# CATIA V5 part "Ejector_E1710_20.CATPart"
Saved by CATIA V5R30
Part number: Vyhazovac_4x160_7
Nomenclature: E1710/4x160
Description: MEUSBURGER
Property "Material": "1.221"
Publications: "__DrillHole", "Base"
Bounding box of the stored display mesh (mm): x -3.996 to 3.996, y -3.999 to 3.999, z 0 to 152
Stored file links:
  E:\Bakalarka\Model\Forma_v7\Ejector_E1710_20.CATPart
  E:\dev\MoldDesign\intel_a\startup\components\MoldCatalog\Ejector\Meusburger\Ejector_E1710\TableE1710.txt
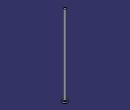
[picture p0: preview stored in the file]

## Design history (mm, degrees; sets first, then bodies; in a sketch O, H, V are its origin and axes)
Parameters
  Ref = "E1710/4x160" {design table}
  D1 = 4 mm {design table}
  D3 = 8 mm {design table}
  L = 160 mm {design table}
  L3 = 3 mm {design table}
  R = 0.3 mm {design table}
  k_d3 = 9 mm {design table}
  k_d1 = 4.2 mm {design table}
  k_F = 0.3 mm {design table}
  kl = 17 mm {design table}
  Mat = "1.221" {design table}
  HeatTreat = "ISO6751" {design table}
  Offset_Parting = 10 mm
  Anti_Rotation = "Normal"
  Anti_Rotation_D = 2.3 mm
  Anti_Rotation_D_Icut = 2.3 mm
  Add_Length_L = 0.8377 mm
  Add_Length_D3 = 0 mm
  SupplierRef = "Meusburger 2017"
  BmpRef = "F_MldEjectorD1"
  DrillHole_Length = 225 mm
  ValidationTest = false
  Anti_Rotation_D_min = 2.3 mm {= OffSet_D1 /2}
  Anti_Rotation_D_max = 3.925 mm {= D3/2-0.075mm}
  Anti_Rotation_D_ref = 2.3 mm {= Anti_Rotation_D}
  Anti_Rotation_D_Icut_ref = 2.3 mm {= Anti_Rotation_D_Icut}
  Anti_Rotation_Ref_Icut = 2.3246 mm
  Offset_L = 20 mm
  D = 4 mm {= D1}
  OffSet_D1 = 4.6 mm {= D1+2*R}
  OffSet_D3 = 9 mm {= D3+1mm}
  XG_Split = 156 mm
  YG_Split = 21.5 mm
  ZG_Split = -198 mm
  DirX_Split = 0 mm
  DirY_Split = 0 mm
  DirZ_Split = 1 mm
Set1 "BaseBody"
  Point1 "Base": (0, 0, 0)
  Plane1: type Offset, RefPlane xy-plane, Offset 225 {= DrillHole_Length}, reversed
  Sketch1 "Sketch.2" on xy-plane, origin (0, 0, 0), H (1, 0, 0), V (0, 1, 0)
    point P1 (-0.46, 1.1623)
    point P2 (0.46, 1.1623)
    construction line L1 (-0.46, 1.1623) -> (0.46, 1.1623)
    point P3 (0.46, -1.1623)
    line L2 (0.46, -1.1623) -> (0.46, 1.1623)
    point P4 (-0.46, -1.1623)
    construction line L3 (0.46, -1.1623) -> (-0.46, -1.1623)
    line L4 (-0.46, 1.1623) -> (-0.46, -1.1623)
    point P5 (-0.21, 1.1623)
    arc A1 centre (-0.21, 1.1623) radius 0.25 from (-0.21, 1.4123) to (-0.46, 1.1623) ccw
    point P7 (0.21, 1.1623)
    point P8 (0.21, 1.4123)
    arc A2 centre (0.21, 1.1623) radius 0.25 from (0.46, 1.1623) to (0.21, 1.4123) ccw
    line L5 (-0.21, 1.4123) -> (0.21, 1.4123)
    point P9 (-0.46, -1.1623)
    arc A3 centre (-0.21, -1.1623) radius 0.25 from (-0.46, -1.1623) to (-0.21, -1.4123) ccw
    point P11 (0.21, -1.4123)
    line L6 (-0.21, -1.4123) -> (0.21, -1.4123)
    point P12 (0.46, -1.1623)
    arc A4 centre (0.21, -1.1623) radius 0.25 from (0.21, -1.4123) to (0.46, -1.1623) ccw
    point P14 (-0.46, 1.1623)
    point P15 (-0.46, -1.1623)
    point P16 (0.46, 1.1623)
    point P17 (0.46, -1.1623)
    reference projected circle E1 centre (0, 0) radius 1.25 from edge [face of Shaft1 from Sketch2.L3 | face of Shaft1 from Sketch2.L4]
    reference projected circle E2 centre (0, 0) radius 1.25 from edge [face of Shaft1 from Sketch2.L3 | face of Shaft1 from Sketch2.L4]
    reference projected circle E3 centre (0, 0) radius 1.25 from edge [face of Shaft1 from Sketch2.L3 | face of Shaft1 from Sketch2.L4]
    reference projected circle E4 centre (0, 0) radius 1.25 from edge [face of Shaft1 from Sketch2.L3 | face of Shaft1 from Sketch2.L4]
    point P18 (-0.46, -1.1623)
    point P19 (-0.21, -1.4123)
    point P20 (0.21, -1.4123)
    point P21 (0.46, -1.1623)
    point P22 (-0.21, -1.4123)
    point P23 (0.21, -1.4123)
    distance P14 P15 = 2.3246 (reference)
    distance P16 P17 = 2.3246 (reference)
    distance L1 P14 = 0 (reference)
    radius A1 = 2
    distance L4 V = 2.31
    distance L2 V = 3.935
    distance L5 L6 = 8
    horizontal: L1 H, L3 H, L5 H
    vertical: L2 V, L4 V
    coincidence: P5 L1, P7 L1, P3 P12, P14 L4, P15 L4, P16 L2, P17 L2, P14 E1, P15 E2, P16 E3, P17 E4, P3 P21, P4 P18, P20 P23, P19 P22
    tangency: A1 L4, A2 L2, A2 L5, A1 L5
    symmetry: P1 P9 H, A1 A3 H, P8 P11 H, L5 L6 H, P2 P12 H, A2 A4 H
  DatumSurface1
  DatumSurface2
Body1 "PartBody" (main body)
  Sketch2 "Sketch.1" on zx-plane, origin (0, 0, 0), H (-1, 0, 0), V (0, 0, 1)
    point P1 (0, 160)
    line L1 (2, 160) -> (0, 160)
    line L2 (2, 3) -> (2, 160)
    line L3 (4, 3) -> (2, 3)
    line L4 (4, 0) -> (4, 3)
    point P5 (0, 0)
    line L5 (0, 0) -> (4, 0)
    point P6 (0, 160)
    axis line L6 (0, 160) -> (0, 0)
    point P7 (0, 0)
    point P8 (2, 3)
    point P9 (2, 3)
    line L7 (0, 160) -> (0, 0)
    distance L5 L3 = 3 {= L3}
    distance L5 L1 = 160 {= L}
    distance L2 L6 = 2 {= D1 /2}
    distance L4 L6 = 4 {= D3 /2}
    coincidence: L6 P5, P1 L6, L5 H, L6 V, P7 O, P6 P1, P8 P9
    vertical: L2 V, L7 V
    horizontal: L1 H
  Shaft1 "Shaft.1": profile Sketch2, axis Sketch2.L6, angle 360
  Pocket1 "Pocket.1": profile Sketch1, direction (0, 0, 1), length 4, outer side, deactivated
  Pocket2 "Pocket.2": profile Sketch1, direction (0, 0, 1), length 4, outer side, deactivated
  Fillet1: radius 0.3 {= R}, on edge [face of Shaft1 from Sketch2.L2 | face of Shaft1 from Sketch2.L3]
  Pocket3: profile face of Shaft1 from Sketch2.L1, direction along face of DatumSurface1, up to face of DatumSurface2
Body2 "__DrillHole"
  Sketch3 "Sketch.3" on face of Shaft1, origin (0, 0, 0), H (1, 0, 0), V (0, -1, 0)
    point P1 (0, 0)
    reference projected point E1 (0, 0) from Point1
    coincidence: E1 P1
  Hole1 "Hole.1": placed by Sketch3, at (0, 0, 0) direction (0, 0, 1), diameter 4.6 {= OffSet_D1}, depth 140 {= L-Offset_L}
  Sketch4 "Sketch.4" on face of Shaft1, origin (0, 0, 0), H (1, 0, 0), V (0, -1, 0)
    point P1 (0, 0)
    reference projected point E1 (0, 0) from Point1
    coincidence: E1 P1
  Hole2 "Hole.2": placed by Sketch4, at (0, 0, 0) direction (0, 0, 1), diameter 4 {= D1}, depth 160 {= L}
  Sketch5 "Sketch.5" on face of Shaft1 from Sketch2.L3, origin (0, 0, 3), H (1, 0, 0), V (0, 1, 0)
    point P1 (0, 0)
    reference projected point E1 (0, 0) from Point1
    coincidence: E1 P1
  Hole3 "Hole.3": placed by Sketch5, at (0, 0, 3) direction (0, 0, -1), diameter 9 {= OffSet_D3}, depth 228 {= L3 +DrillHole_Length}
  Chamfer1: length 0.3 {= k_F}, angle 45, on edge [face of Hole1 | face of Hole3]
  Body3 "__Body.1"
    Pocket4 "Pocket.3": profile Sketch1, direction (0, 0, -1), length 225, opposite side length 3, deactivated
  Assemble1: tool Body3
  Chamfer2: length 0.3 {= k_F}, angle 45, on edge [start face of Pocket4 | face of Hole1], deactivated
  Body4 "__Body.2"
    Pocket5 "Pocket.4": profile Sketch1, direction (0, 0, -1), length 225, opposite side length 3, deactivated
  Assemble2: tool Body4
  Chamfer3: length 0.3 {= k_F}, angle 45, on edge [start face of Pocket5 | face of Hole1], deactivated
Relations
  design table "TableE1710", configuration 187, drives Ref, D1, D3, L, L3, R, k_d3, k_d1, k_F, kl, Mat, HeatTreat
  Offset_L = 20mm (deactivated)
  rule "Cut_Head_rule":
    let sketch_cut (length)
    let PartBody_Pocket_Sketch (Boolean)
    let I_PartBody_Pocket (Boolean)
    let D_PartBody_Pocket (Boolean)
    let N_DrillHole_Hole (Boolean)
    let N_DrillHole_Hole_Sketch (Boolean)
    let I_DrillHole_Pocket (Boolean)
    let D_DrillHole_Pocket (Boolean)
    /* --------------------------------------------------------------------------------------*/
    if Anti_Rotation =="Normal"
    {
    	sketch_cut=Anti_Rotation_D_max
    	PartBody_Pocket_Sketch = false
    	I_PartBody_Pocket = false
    	D_PartBody_Pocket = false
    	N_DrillHole_Hole = true
    	N_DrillHole_Hole_Sketch = true
    	I_DrillHole_Pocket = false
    	D_DrillHole_Pocket = false
    	Chamfer1.Activity= true
    	Chamfer2.Activity= false
    	Chamfer3.Activity= false
    }
    if Anti_Rotation == "I_Cut"
    {
    	sketch_cut=Anti_Rotation_D_Icut_ref
    	PartBody_Pocket_Sketch = true
    	I_PartBody_Pocket = true
    	D_PartBody_Pocket = false
    	N_DrillHole_Hole = false
    	N_DrillHole_Hole_Sketch = false
    	I_DrillHole_Pocket = true
    	D_DrillHole_Pocket = false
    	Chamfer1.Activity= false
    	Chamfer2.Activity= true
    	Chamfer3.Activity= false
    }
    if Anti_Rotation =="D_Cut"
    {
    	sketch_cut=Anti_Rotation_D_max
    	PartBody_Pocket_Sketch = true
    	I_PartBody_Pocket = false
    	D_PartBody_Pocket = true
    	N_DrillHole_Hole = false
    	N_DrillHole_Hole_Sketch = false
    	I_DrillHole_Pocket = false
    	D_DrillHole_Pocket = true
    	Chamfer1.Activity= false
    	Chamfer2.Activity= false
    	Chamfer3.Activity= true
    }
    /* --------------------------------------------------------------------------------------*/
    Sketch1.distance(L2 V) = sketch_cut+0.01mm
    Sketch1.distance(L4 V) =Anti_Rotation_D_ref+0.01mm
    Sketch1.radius(A1) =D/2
    Pocket4.FirstLimit.Depth = DrillHole_Length
    Pocket5.FirstLimit.Depth = DrillHole_Length
    Pocket1.FirstLimit.Depth = L3+1mm
    Pocket2.FirstLimit.Depth = L3+1mm
    Pocket4.SecondLimit.Depth = L3
    Pocket5.SecondLimit.Depth =L3
    Pocket1.Activity = I_PartBody_Pocket
    Pocket2.Activity = D_PartBody_Pocket
    Sketch1.Activity =PartBody_Pocket_Sketch
    Hole3.Activity= N_DrillHole_Hole
    Sketch5.Activity = N_DrillHole_Hole_Sketch
    Pocket4.Activity = I_DrillHole_Pocket
    Pocket5.Activity  = D_DrillHole_Pocket
  rule "Anti_Rotation_Icut_constrain":
    let Ref1(length)
    let Ref2(length)
    let Ref3(length)
    let Diam1(length)
    let Diam2(length)
    let Add_Length_Lmin (length)
    Ref1=Sketch1.distance(P14 P15)
    Ref2=Sketch1.distance(P16 P17)
    Diam1=D
    Diam2=D3
    /* --------------------------------------------------------------------*/
    if Ref1 >Ref2
    	Anti_Rotation_Ref_Icut = Ref1
    else
    	Anti_Rotation_Ref_Icut  =Ref2
    Add_Length_D3 .InferiorRange=Anti_Rotation_Ref_Icut /2+Diam1/2 -Diam2/2
    if Add_Length_D3 .InferiorRange<0mm
    	Add_Length_D3 .InferiorRange=0mm
    if ValidationTest == "true"
    	Ref3   = 2*Add_Length_L +Anti_Rotation_Ref_Icut  +2*Diam1/2
    else
    	Ref3  =Diam2+2*Add_Length_D3
    if Ref3 <Diam2
    {
    	Ref3 =Diam2
    }
    /* --------------------------------------------------------------------*/
    Sketch1.distance(L5 L6) = Ref3
    Add_Length_L .InferiorRange=Diam2/2-Anti_Rotation_Ref_Icut/2-Diam1/2
    Add_Length_Lmin=Diam2/2-Anti_Rotation_Ref_Icut/2-Diam1/2
    if Add_Length_Lmin<0mm
    	Add_Length_L .InferiorRange=0mm
    else
    	Add_Length_L .InferiorRange=Add_Length_Lmin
